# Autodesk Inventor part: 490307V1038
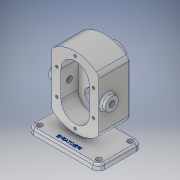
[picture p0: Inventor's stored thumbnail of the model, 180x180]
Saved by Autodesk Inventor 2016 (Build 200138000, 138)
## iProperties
Created: 2019-03
Part Number: 490307V1038
Material: 알루미늄 6061
Document SubType Name: Modeling
Designer: 605-11
Density: 2.7 g/cm^3
Appearance: 알루미늄 - 평지
Mass: 1183.68 g
Surface Area: 721.542 cm^2
Volume: 438.399 cm^3
Author: 605-11
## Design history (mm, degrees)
sketch "스케치1"
  geometry: L1 (50, 36.5)-(-50, 36.5); L2 (-60, 26.5)-(-60, -26.5); L3 (-50, -36.5)-(50, -36.5); L4 (60, -26.5)-(60, 26.5); L5 (60, 36.5)-(-60, -36.5); L6 (-60, 36.5)-(60, -36.5); C1 r 4.5 at (50, 26.5); C2 r 4.5 at (50, -26.5); C3 r 4.5 at (-50, -26.5); C4 r 4.5 at (-50, 26.5); A1 r 10 centre (50, 26.5) between (60, 26.5) and (50, 36.5); A2 r 10 centre (50, -26.5) between (50, -36.5) and (60, -26.5); A3 r 10 centre (-50, 26.5) between (-50, 36.5) and (-60, 26.5); A4 r 10 centre (-50, -26.5) between (-60, -26.5) and (-50, -36.5); 1 further point
  constraints: 12 end point, 8 centre point, 8 point on circle, 8 point on line, 8 tangent, 4 coincident, 3 equal radius, 2 midpoint, 2 parallel, 1 horizontal, 1 perpendicular
  dimensions: "d0" = 73 distance of L6.end L5.start; "d1" = 120 distance of L5.start L6.start; "d2" = 10 radius of A1; "d3" = 9 diameter of C1; "d4" = 9 diameter of C2; "d5" = 9 diameter of C3; "d6" = 9 diameter of C4
extrude "돌출1" new body sketch "스케치1" distance "d7" = 10; taper "d8" = 0 deg
sketch "스케치2"
  geometry: L1 (10, -108)-(10, -28); L2 (90, -28)-(90, -108); L3 (0, 0)-(100, 0) reference; L4 (90, -68)-(10, -68); L5 (0, 10)-(100, 10) reference; A1 r 60 centre (50, -68) between (86, -20) and (14, -20); A2 r 60 centre (50, -68) between (14, -116) and (86, -116); A3 r 10 centre (80, -108) between (86, -116) and (90, -108); A4 r 10 centre (20, -108) between (10, -108) and (14, -116); A5 r 10 centre (20, -28) between (14, -20) and (10, -28); A6 r 10 centre (80, -28) between (90, -28) and (86, -20); 7 further points
  constraints: 16 point on circle, 8 tangent, 6 centre point, 6 end point, 4 midpoint, 4 point on line, 3 equal radius, 1 parallel, 1 vertical alignment
  dimensions: "d10" = 78 distance from line of L5 L4.start; "d14" = 80 distance between parallel lines of L1 L2; "d15" = 10 radius of A3
extrude "돌출2" join sketch "스케치2" distance "d16" = 53; taper "d17" = 0 deg
sketch "스케치3"
  geometry: L1 (0, 0)-(100, 0) reference; L2 (56, 0)-(44, 0); L3 (44, 0)-(44, -12.849); L4 (44, -12.849)-(56, -12.849); L5 (56, -12.849)-(56, 0); 3 further points
  constraints: 8 end point, 2 midpoint, 2 parallel, 1 horizontal, 1 perpendicular, 1 point on line, 1 vertical alignment
  dimensions: "d18" = 12 distance of L3.end L4.end
extrude "돌출3" join sketch "스케치3" distance "d19" = 43; taper "d20" = 0 deg
sketch "스케치4"
  geometry: L1 (-10, -28)-(-10, -108) reference; L2 (-90, -108)-(-90, -28) reference; L3 (10, 10)-(10, 0) reference; L4 (10, 0)-(-110, 0) reference; L5 (-110, 0)-(-110, 10) reference; L6 (-110, 10)-(10, 10) reference; L7 (-50, -90)-(-50, -46); L8 (-26, -90)-(-26, -46); L9 (-74, -46)-(-74, -90); L10 (-100, 0)-(0, 0) reference; A1 r 60 centre (-50, -68) between (-14, -20) and (-86, -20) reference; A2 r 10 centre (-20, -28) between (-10, -28) and (-14, -20) reference; A3 r 10 centre (-20, -108) between (-14, -116) and (-10, -108) reference; A4 r 60 centre (-50, -68) between (-86, -116) and (-14, -116) reference; A5 r 10 centre (-80, -108) between (-90, -108) and (-86, -116) reference; A6 r 10 centre (-80, -28) between (-86, -20) and (-90, -28) reference; A7 r 24 centre (-50, -90) between (-74, -90) and (-26, -90); A8 r 24 centre (-50, -46) between (-26, -46) and (-74, -46); 3 further points
  constraints: 8 end point, 4 point on circle, 4 tangent, 2 centre point, 2 midpoint, 1 coincident, 1 parallel, 1 vertical, 1 vertical alignment
  dimensions: "d21" = 44 distance of L7.start L7.end; "d22" = 48 diameter of A8
extrude "돌출4" cut sketch "스케치4" distance "d24" = 29; taper "d25" = 0 deg
node "작업 평면1"
sketch "스케치5"
  geometry: L1 (-10, 22.469)-(0, 22.469) reference; L2 (0, 22.469)-(0, -22.469) reference; L3 (0, -22.469)-(-10, -22.469) reference; L4 (-10, -22.469)-(-10, 22.469) reference; L5 (0, -36.5)-(-10, -36.5) reference; L6 (-10, -36.5)-(-10, -30.531) reference; L7 (-10, -30.531)-(0, -30.531) reference; L8 (0, -30.531)-(0, -36.5) reference; L9 (-10, 36.5)-(0, 36.5) reference; L10 (0, 36.5)-(0, 30.531) reference; L11 (0, 30.531)-(-10, 30.531) reference; L12 (-10, 30.531)-(-10, 36.5) reference; L13 (108, -36.5)-(28, -36.5) reference; L14 (108, -36.5)-(108, 16.5) reference; L15 (28, 16.5)-(108, 16.5) reference; L16 (28, -36.5)-(28, 16.5) reference; L17 (-10, -26.5)-(-10, 26.5) reference; C1 r 11 at (68, 2.5); 2 further points
  constraints: 1 centre point, 1 midpoint, 1 vertical alignment
  dimensions: "d27" = 22 diameter of C1; "d28" = 14 distance from line of L15 C1.centre; "d29" = 78 distance from line of L17 C1.centre (derived)
extrude "돌출5" join sketch "스케치5" stored distance "d30" = 29; taper "d31" = 0 deg
hole "구멍1" diameter "d34" = 10; stored, may be unused: countersink angle "d38" = 90 deg, drill point angle "d40" = 0 deg; dims "d35" = 20, "d36" = 4, "d37" = 2, "d39" = 25.1, "d89" = 10, "d90" = 10
sketch "스케치6"
  geometry: L1 (-100, 0)-(0, 0) reference; L2 (-50, -90)-(-50, -46); L3 (-74, -46)-(-74, -90) reference; L4 (-26, -90)-(-26, -46) reference; L5 (10, 10)-(10, 0) reference; L6 (10, 0)-(-44, 0) reference; L7 (-44, 0)-(-44, -8.301) reference; L8 (-10, -28)-(-10, -108) reference; L9 (-90, -108)-(-90, -28) reference; L10 (-56, -8.301)-(-56, 0) reference; L11 (-56, 0)-(-110, 0) reference; L12 (-110, 0)-(-110, 10) reference; L13 (-110, 10)-(10, 10) reference; L14 (-26, -46)-(-26, -90) reference; C1 r 12.5 at (-50, -46); C2 r 12.5 at (-50, -90); A1 r 24 centre (-50, -90) between (-74, -90) and (-26, -90) reference; A2 r 24 centre (-50, -46) between (-26, -46) and (-74, -46) reference; A3 r 60 centre (-50, -68) between (-14, -20) and (-44, -8.301) reference; A4 r 10 centre (-20, -28) between (-10, -28) and (-14, -20) reference; A5 r 10 centre (-20, -108) between (-14, -116) and (-10, -108) reference; A6 r 60 centre (-50, -68) between (-86, -116) and (-14, -116) reference; A7 r 10 centre (-80, -108) between (-90, -108) and (-86, -116) reference; A8 r 10 centre (-80, -28) between (-86, -20) and (-90, -28) reference; A9 r 60 centre (-50, -68) between (-56, -8.301) and (-86, -20) reference; 5 further points
  constraints: 4 midpoint, 2 centre point, 2 end point, 2 vertical alignment, 1 horizontal alignment, 1 vertical
  dimensions: "d42" = 25 diameter of C1; "d43" = 25 diameter of C2; "d44" = 44 distance of L2.start L2.end
extrude "돌출6" cut sketch "스케치6" distance "d45" = 15; taper "d46" = 0 deg
node "작업 평면3"
sketch "스케치7"
  geometry: L1 (0, -10)-(0, 0) reference; L2 (0, 0)-(100, 0) reference; L3 (100, -10)-(100, 0) reference; L4 (100, -10)-(56, -10) reference; L5 (56, -10)-(56, -18.301) reference; L6 (90, -38)-(90, -118) reference; L7 (10, -118)-(10, -38) reference; L8 (44, -18.301)-(44, -10) reference; L9 (44, -10)-(0, -10) reference; L10 (0, -10)-(44, -10) reference; L11 (44, -10)-(44, -18.301) reference; L12 (10, -38)-(10, -118) reference; L13 (90, -118)-(90, -38) reference; L14 (56, -18.301)-(56, -10) reference; L15 (56, -10)-(100, -10) reference; L16 (100, -10)-(100, 0) reference; L17 (0, 0)-(100, 0) reference; L18 (0, -10)-(0, 0) reference; C1 r 12.5 at (50, -100) reference; C2 r 19 at (50, -100); A1 r 60 centre (50, -78) between (86, -30) and (56, -18.301) reference; A2 r 10 centre (80, -38) between (90, -38) and (86, -30) reference; A3 r 10 centre (80, -118) between (86, -126) and (90, -118) reference; A4 r 60 centre (50, -78) between (14, -126) and (86, -126) reference; A5 r 10 centre (20, -118) between (10, -118) and (14, -126) reference; A6 r 10 centre (20, -38) between (14, -30) and (10, -38) reference; A7 r 60 centre (50, -78) between (44, -18.301) and (14, -30) reference; A8 r 60 centre (50, -78) between (44, -18.301) and (14, -30) reference; A9 r 10 centre (20, -38) between (14, -30) and (10, -38) reference; A10 r 10 centre (20, -118) between (10, -118) and (14, -126) reference; A11 r 60 centre (50, -78) between (14, -126) and (86, -126) reference; A12 r 10 centre (80, -118) between (86, -126) and (90, -118) reference; A13 r 10 centre (80, -38) between (90, -38) and (86, -30) reference; A14 r 60 centre (50, -78) between (86, -30) and (56, -18.301) reference; 1 further point
  constraints: 1 centre point, 1 coincident
  dimensions: "d47" = 38 diameter of C2
extrude "돌출7" join sketch "스케치7" distance "d48" = 17; taper "d49" = 0 deg
hole "구멍2" diameter "d52" = 17; stored, may be unused: countersink angle "d56" = 90 deg, drill point angle "d58" = 0 deg; dims "d50" = 10, "d51" = 10, "d53" = 20, "d54" = 4, "d55" = 2, "d57" = 25.1
hole "구멍3" diameter "d61" = 28; stored, may be unused: countersink angle "d65" = 90 deg, drill point angle "d67" = 0 deg; dims "d59" = 10, "d60" = 10, "d62" = 20, "d63" = 4, "d64" = 2, "d66" = 7.3
sketch "스케치8"
  geometry: L1 (-26, -46)-(-26, -90) reference; L2 (-74, -90)-(-74, -46) reference; L3 (-90, -28)-(-90, -108) reference; L4 (-10, -108)-(-10, -28) reference; L5 (-19, -90)-(-19, -46); L6 (-81, -90)-(-81, -46); C1 r 8.5 at (-50, -90) reference; A1 r 24 centre (-50, -46) between (-26, -46) and (-74, -46) reference; A2 r 24 centre (-50, -90) between (-74, -90) and (-26, -90) reference; A3 r 10 centre (-80, -108) between (-90, -108) and (-86, -116) reference; A4 r 60 centre (-50, -68) between (-86, -116) and (-14, -116) reference; A5 r 10 centre (-20, -108) between (-14, -116) and (-10, -108) reference; A6 r 10 centre (-20, -28) between (-10, -28) and (-14, -20) reference; A7 r 60 centre (-50, -68) between (-14, -20) and (-86, -20) reference; A8 r 10 centre (-80, -28) between (-86, -20) and (-90, -28) reference; A9 r 31 centre (-50, -46) between (-28.16, -68) and (-26, -65.621); A10 r 31 centre (-50, -90) between (-26, -70.379) and (-28.16, -68); A11 r 31 centre (-50, -46) between (-19, -46) and (-81, -46); A12 r 31 centre (-50, -46) between (-74, -65.621) and (-71.84, -68); A13 r 31 centre (-50, -90) between (-71.84, -68) and (-74, -70.379); A14 r 31 centre (-50, -90) between (-81, -90) and (-19, -90); 7 further points
  constraints: 14 point on circle, 6 centre point, 6 coincident, 4 end point, 4 horizontal alignment, 4 point on line, 3 tangent, 2 vertical alignment, 1 vertical
hole "구멍4" sketch "스케치8" at (-50, -121), (-50, -15), (-19, -46), (-81, -46), (-81, -90), (-19, -90) diameter "d70" = 4.459; stored, may be unused: countersink angle "d74" = 90 deg, drill point angle "d76" = 118 deg; dims "d71" = 10, "d72" = 4, "d73" = 2, "d75" = 12
chamfer "모따기1" distance "d77" = 0.7; stored, may be unused: second distance "d78" = 2, angle "d79" = 30 deg
fillet "모깎기2" dims "d80" = 0.5
fillet "모깎기3" dims "d81" = 3
sketch "스케치9"
  geometry: L1 (50, 36.5)-(-50, 36.5) reference; L2 (60, -26.5)-(60, 26.5) reference; 2 further points
  constraints: 1 other
  dimensions: "d82" = 10 distance from line of L1 point (0, 26.5); "d83" = 60 distance from line of L2 point (0, 26.5)
feature "엠보싱1" sketch "스케치9" dims "d0" = 73, "d1" = 120, "d2" = 10, "d3" = 9, "d4" = 9, "d5" = 9, "d6" = 9, "d84" = 0.5, "d85" = 0
chamfer "모따기2" distance "d86" = 1; stored, may be unused: second distance "d87" = 2, angle "d88" = 30 deg
feature "스레드1" dims "d91" = 10, "d92" = 0
feature "스레드2" dims "d93" = 10, "d94" = 0
node "솔리드1"
mirror "대칭1"
node "투영된 루프1"
node "투영된 루프2"
node "투영된 루프3"
node "절단 모서리 투영1"
node "절단 모서리 투영2"
node "절단 모서리 투영3"
node "절단 모서리 투영4"
other parameters: "d26" = -48, "d68" = 62, "d69" = 62
